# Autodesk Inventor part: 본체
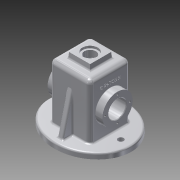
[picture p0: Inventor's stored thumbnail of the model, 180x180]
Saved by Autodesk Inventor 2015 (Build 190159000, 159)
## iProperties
Created: 2017-07
Part Number: 본체
Material: 알루미늄 6061
Document SubType Name: Modeling
Designer: Administrator
Density: 2.7 g/cm^3
Appearance: 알루미늄 - 평지
Mass: 889.522 g
Surface Area: 988.916 cm^2
Volume: 329.453 cm^3
Author: Administrator
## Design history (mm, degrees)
sketch "스케치1" dims "d0" = 75, "d1" = 65
  geometry: L1 (0, 0)-(101.209, 0); L2 (0, 0)-(0, 77.977); 1 further point; 1 other entity
  constraints: 4 end point, 1 coincident, 1 horizontal, 1 vertical, 2 other
extrude "돌출1" new body sketch "스케치1" distance "d2" = 10; taper "d3" = 0 deg
sketch "스케치2"
  geometry: L1 (0, 0)-(71.656, 0); L2 (0, 0)-(0, 41.948); 2 further points
  constraints: 4 end point, 1 horizontal, 1 point on line, 1 symmetric about line, 1 vertical
  dimensions: "d4" = 56 distance of point (56, 0) L1.start
hole "구멍1" sketch "스케치2" at (56, 0), (-56, 0) diameter "d5" = 10; stored, may be unused: countersink angle "d9" = 90 deg, drill point angle "d11" = 118 deg; dims "d6" = 6, "d7" = 4, "d8" = 2, "d10" = 8
sketch "스케치3"
  geometry: L1 (-37, 37)-(37, 37); L2 (37, 37)-(37, -37); L3 (37, -37)-(-37, -37); L4 (-37, -37)-(-37, 37); L5 (-37, 37)-(37, -37); 2 further points
  constraints: 10 end point, 2 parallel, 1 coincident, 1 horizontal, 1 midpoint, 1 perpendicular
  dimensions: "d12" = 74 distance of L3.end L1.start; "d13" = 74 distance of L1.start L1.end
extrude "돌출2" join sketch "스케치3" distance "d14" = 100; taper "d15" = 0 deg
sketch "스케치4"
  geometry: L1 (37, 37)-(-37, 37) reference; L2 (-37, 37)-(-37, -37) reference; L3 (-37, -37)-(37, -37) reference; L4 (37, -37)-(37, 37) reference; L5 (-20, 20)-(20, 20); L6 (20, 20)-(20, -20); L7 (20, -20)-(-20, -20); L8 (-20, -20)-(-20, 20); L9 (-20, 20)-(20, -20); 2 further points
  constraints: 10 end point, 2 parallel, 1 coincident, 1 horizontal, 1 midpoint, 1 perpendicular
  dimensions: "d16" = 40 distance of L6.end L7.end; "d17" = 40 distance of L7.end L5.start
extrude "돌출3" join sketch "스케치4" distance "d18" = 10; taper "d19" = -5 deg
sketch "스케치5"
  geometry: L1 (-32, 32)-(32, 32); L2 (32, 32)-(32, -32); L3 (32, -32)-(-32, -32); L4 (-32, -32)-(-32, 32); L5 (-32, 32)-(32, -32); 2 further points
  constraints: 10 end point, 2 parallel, 1 coincident, 1 horizontal, 1 midpoint, 1 perpendicular
  dimensions: "d20" = 64 distance of L2.end L3.end; "d21" = 64 distance of L3.end L1.start
extrude "돌출4" cut sketch "스케치5" distance "d22" = 105; taper "d23" = 0 deg
sketch "스케치6"
  geometry: 2 further points
  constraints: 1 coincident
hole "구멍2" sketch "스케치6" at (0, 0) diameter "d24" = 21; stored, may be unused: countersink angle "d28" = 90 deg, drill point angle "d30" = 118 deg; dims "d25" = 6, "d26" = 28, "d27" = 4, "d29" = 8
sketch "스케치7"
  geometry: L1 (81.593, 55)-(-81.593, 55); L2 (50, 55)-(50, 82.5); L3 (50, 82.5)-(32, 82.5); L4 (32, 0)-(32, 105) reference; L5 (32, 82.5)-(25, 75.5); L6 (25, 75.5)-(25, 55); L7 (-50, 55)-(-50, 82.5); L8 (-50, 82.5)-(-32, 82.5); L9 (-32, 0)-(-32, 105) reference; L10 (-32, 82.5)-(-25, 75.5); L11 (-25, 75.5)-(-25, 55); L12 (0, 0)-(0, 80.891); L13 (-37, 10)-(-37, 110) reference; 1 further point
  constraints: 20 end point, 7 point on line, 3 perpendicular, 3 vertical, 2 horizontal, 1 midpoint
  dimensions: "d31" = 55 distance from line of L12.start L1; "d32" = 55 diameter of L3 L1; "d33" = 135 deg angle of L4 L5; "d34" = 55 diameter of L8 L1; "d35" = 135 deg angle of L9 L10; "d36" = 7 distance between parallel lines of L6 L4; "d37" = 7 distance between parallel lines of L9 L11; "d38" = 100 distance between parallel lines of L7 L2; "d39" = 13 distance between parallel lines of L7 L13
revolve "회전1" sketch "스케치7" stored, may be unused: angle "d40" = 90 deg
sketch "스케치8"
  geometry: C1 r 27.5 at (0, 0) reference; C2 r 16 at (0, 0); 1 further point
  constraints: 1 centre point, 1 coincident
  dimensions: "d41" = 32 diameter of C2
extrude "돌출5" cut sketch "스케치8" stored distance "d42" = 105; taper "d43" = 0 deg
sketch "스케치9"
  geometry: L1 (0, 0)-(48.104, 0); C1 r 27.5 at (0, 0) reference; 5 further points
  constraints: 2 end point, 1 horizontal, 1 point on line, 5 other
  dimensions: "d44" = 22.5 distance of point (22.5, 0) L1.start; "d47" = 360 deg dimension on L1.start point (22.5, 0) (derived)
hole "구멍3" sketch "스케치9" at (22.5, 0), (0, 22.5), (-22.5, 0), (0, -22.5) diameter "d49" = 3.242; stored, may be unused: countersink angle "d53" = 90 deg, drill point angle "d55" = 118 deg; dims "d50" = 8, "d51" = 28, "d52" = 4, "d54" = 10
sketch "스케치10"
  geometry: L1 (0, 0)-(-39.346, 0); L2 (0, 0)-(0, -39.346); L3 (0, 0)-(39.346, 0); L4 (0, 0)-(0, 39.346); C1 r 27.5 at (0, 0) reference; 5 further points
  constraints: 8 end point, 4 point on line, 2 coincident, 1 horizontal, 15 other
  dimensions: "d56" = 22.5 distance of L1.start point (-22.5, 0); "d59" = 360 deg dimension on L1.start L1.end (derived)
hole "구멍4" sketch "스케치10" at (-22.5, 0), (0, -22.5), (22.5, 0), (0, 22.5) diameter "d61" = 3.242; stored, may be unused: countersink angle "d65" = 90 deg, drill point angle "d67" = 118 deg; dims "d62" = 8, "d63" = 28, "d64" = 4, "d66" = 10
sketch "스케치11"
  geometry: L1 (65, 10)-(-65, 10) reference; L2 (-37, 10)-(-37, 110) reference; L3 (-55, 10)-(-37, 82.194); L4 (0, 0)-(0, 54.955); L5 (55, 10)-(37, 82.194)
  constraints: 6 end point, 2 point on line, 2 symmetric about line, 1 vertical
  dimensions: "d68" = 10 distance of L1.end L3.start; "d70" = 14 deg angle of L2 L3
feature "리브1" dims "d71" = 1, "d72" = 10, "d73" = 0, "d74" = 0, "d75" = 1, "d76" = 1
feature "리브2" dims "d77" = 1, "d78" = 10, "d79" = 0, "d80" = 0, "d81" = 1, "d82" = 1
fillet "모깎기1" dims "d83" = 3
fillet "모깎기2" dims "d84" = 0.5
fillet "모깎기3" dims "d85" = 0.5
fillet "모깎기4" dims "d86" = 3
fillet "모깎기5" dims "d87" = 8
fillet "모깎기6" dims "d88" = 8
fillet "모깎기9" dims "d91" = 3
chamfer "모따기1" distance "d92" = 1; stored, may be unused: second distance "d93" = 2, angle "d94" = 45 deg
fillet "모깎기10" dims "d95" = 3
fillet "모깎기11" dims "d96" = 3
node "작업 평면1"
sketch "스케치12"
  geometry: L1 (9.186, 9.113)-(9.186, 48.887); L2 (9.186, 48.887)-(14.814, 48.887); L3 (14.814, 48.887)-(14.814, 9.113); L4 (14.814, 9.113)-(9.186, 9.113); L5 (12, 9.113)-(12, 48.887); L6 (-18, 48.125)-(-18, 9.875) reference; L7 (14.814, 29)-(9.186, 29); L8 (89, 66)-(0, 66) reference; 1 further point
  constraints: 4 end point, 4 midpoint, 2 other
  dimensions: "d98" = 30 distance between parallel lines of L6 L5; "d99" = 37 distance between parallel lines of L8 L7
feature "엠보싱1" sketch "스케치12" dims "d0" = 75, "d1" = 65, "d100" = 1, "d101" = 0
node "솔리드1"
node "투영된 루프1"
other parameters: "d97" = 1
